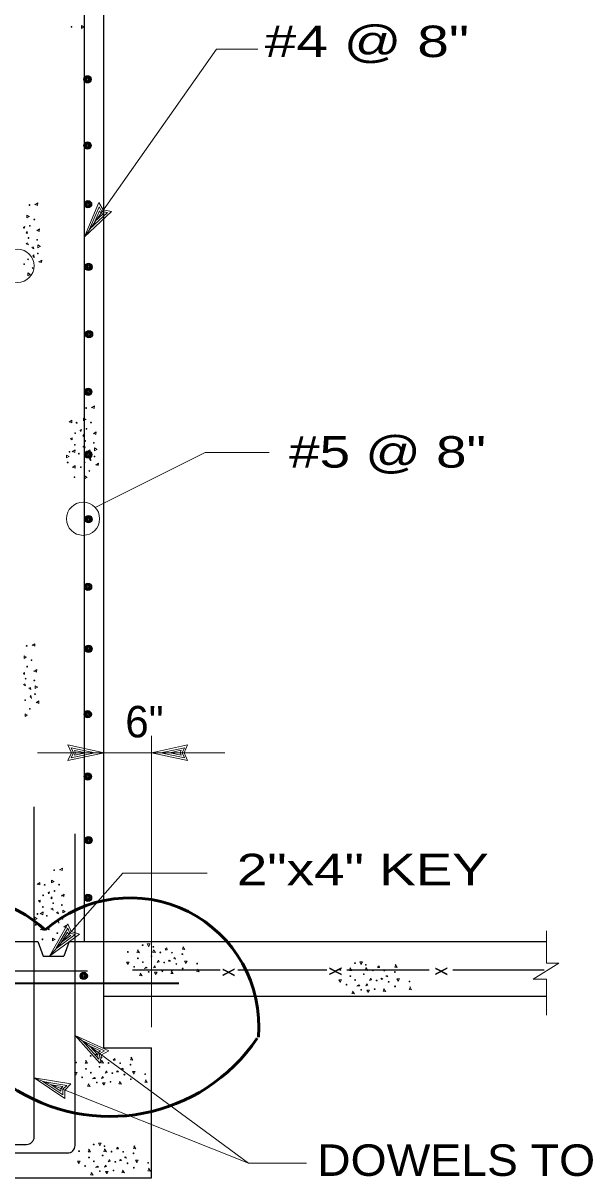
# Model space of a CAD drawing. Extents: x -28.1 to 13.9, y -16.1 to 13.9.
# Drawn here: x -8.685 to -6.424, y 2.995 to 7.58 of the extents above; entities that cross this region are included whole.
import ezdxf
from ezdxf.enums import TextEntityAlignment as Align

# ---------------------------------------------------------------- set-up
doc = ezdxf.new("R2010")
doc.units = 0
doc.header["$LTSCALE"] = 0.05
doc.layers.add('1', color=7, linetype='Continuous', lineweight=13)
doc.layers.add('2', color=7, linetype='Continuous', lineweight=13)

msp = doc.modelspace()

# ---------------------------------------------------------------- linework, layer by layer
at = {"layer": '1', "lineweight": 25}
for p, q in [((-8.36404, 3.51169), (-8.36404, 10.50069)), ((-8.44204, 3.93369), (-8.44204, 8.14169)), ((-8.64104, 3.15769), (-8.64104, 4.46769)), ((-8.47904, 3.12369), (-8.47904, 4.36069)), ((-8.62604, 3.93369), (-8.60504, 3.87569)), ((-8.50204, 3.93369), (-8.52304, 3.87569)), ((-8.50204, 3.93369), (-6.60804, 3.93369)), ((-8.60504, 3.87569), (-8.52304, 3.87569)), ((-9.59204, 3.81669), (-8.42904, 3.81669)), ((-8.25104, 3.82069), (-7.90304, 3.82069)), ((-7.83304, 3.82069), (-7.47904, 3.82069)), ((-7.40004, 3.82069), (-7.07404, 3.82069)), ((-6.98004, 3.82069), (-6.61704, 3.82069)), ((-8.36304, 3.71569), (-6.60804, 3.71569)), ((-8.36404, 3.51169), (-8.17604, 3.51169)), ((-8.17604, 2.99469), (-8.17604, 3.51169)), ((-9.57604, 3.12769), (-8.67104, 3.12769)), ((-8.81704, 3.09369), (-8.50904, 3.09369)), ((-9.67004, 2.99469), (-8.17604, 2.99469))]:
    msp.add_line(p, q, dxfattribs=at)
at = {"layer": '1'}
for p, q in [((-8.44204, 6.73169), (-8.38404, 6.86769)), ((-8.44204, 6.73169), (-8.33404, 6.83169)), ((-8.42104, 6.76169), (-8.38304, 6.85069)), ((-8.40004, 6.79169), (-8.38204, 6.83369)), ((-8.38304, 6.85069), (-8.37204, 6.83169)), ((-8.38204, 6.83369), (-8.37604, 6.82469)), ((-8.37204, 6.83169), (-8.35004, 6.82769)), ((-8.42104, 6.76169), (-8.35004, 6.82769)), ((-8.40004, 6.79169), (-8.36704, 6.82269)), ((-8.37604, 6.82469), (-8.36704, 6.82269)), ((-8.17604, 3.59369), (-8.17604, 4.74969)), ((-8.36304, 4.68269), (-8.50704, 4.71369)), ((-8.36304, 4.68269), (-8.50704, 4.65169)), ((-8.40004, 4.68269), (-8.49404, 4.70269)), ((-8.48504, 4.68269), (-8.49404, 4.70269)), ((-8.40004, 4.68269), (-8.49404, 4.66269)), ((-8.49404, 4.66269), (-8.48504, 4.68269)), ((-8.43604, 4.68269), (-8.48104, 4.69169)), ((-8.47704, 4.68269), (-8.48104, 4.69169)), ((-8.43604, 4.68269), (-8.48104, 4.67269)), ((-8.48104, 4.67269), (-8.47704, 4.68269)), ((-8.17604, 4.68269), (-8.03204, 4.71369)), ((-8.17604, 4.68269), (-8.03204, 4.65169)), ((-8.13904, 4.68269), (-8.04504, 4.70269)), ((-8.13904, 4.68269), (-8.04504, 4.66269)), ((-8.10304, 4.68269), (-8.05804, 4.69269)), ((-8.10304, 4.68269), (-8.05804, 4.67369)), ((-8.05804, 4.69269), (-8.06204, 4.68269)), ((-8.06204, 4.68269), (-8.05804, 4.67369)), ((-8.04504, 4.70269), (-8.05404, 4.68269)), ((-8.05404, 4.68269), (-8.04504, 4.66269)), ((-8.58004, 3.87569), (-8.50804, 4.00369)), ((-8.58004, 3.87569), (-8.46104, 3.96269)), ((-8.55504, 3.90369), (-8.50804, 3.98669)), ((-8.55504, 3.90369), (-8.47804, 3.96069)), ((-8.53204, 3.93069), (-8.50904, 3.97069)), ((-8.53204, 3.93069), (-8.49504, 3.95769)), ((-8.50904, 3.97069), (-8.50404, 3.96069)), ((-8.50804, 3.98669), (-8.49904, 3.96669)), ((-8.50404, 3.96069), (-8.49504, 3.95769)), ((-8.49904, 3.96669), (-8.47804, 3.96069)), ((-6.60804, 3.84769), (-6.60804, 3.97569)), ((-6.66004, 3.78369), (-6.55904, 3.84769)), ((-6.60804, 3.84769), (-6.55904, 3.84769)), ((-6.66004, 3.78369), (-6.60804, 3.78369)), ((-6.60804, 3.64069), (-6.60804, 3.78369)), ((-8.47904, 3.56069), (-7.79004, 3.05269)), ((-8.47904, 3.56069), (-8.34504, 3.49969)), ((-8.47904, 3.56069), (-8.38104, 3.45069)), ((-8.44904, 3.53869), (-8.36204, 3.49869)), ((-8.44904, 3.53869), (-8.38504, 3.46669)), ((-8.42004, 3.51769), (-8.38904, 3.48369)), ((-8.42004, 3.51769), (-8.37804, 3.49869)), ((-8.38704, 3.49269), (-8.38904, 3.48369)), ((-8.37804, 3.49869), (-8.38704, 3.49269)), ((-8.38104, 3.48869), (-8.38504, 3.46669)), ((-8.36204, 3.49869), (-8.38104, 3.48869)), ((-8.64104, 3.39169), (-7.79004, 3.05269)), ((-8.64104, 3.39169), (-8.49604, 3.36769)), ((-8.64104, 3.39169), (-8.51904, 3.30969)), ((-8.60704, 3.37769), (-8.51204, 3.36169)), ((-8.60704, 3.37769), (-8.52704, 3.32469)), ((-8.57304, 3.36469), (-8.53504, 3.33969)), ((-8.57304, 3.36469), (-8.52804, 3.35769)), ((-8.52804, 3.35769), (-8.53504, 3.34969)), ((-8.53504, 3.34969), (-8.53504, 3.33969)), ((-8.51204, 3.36169), (-8.52804, 3.34669)), ((-8.52804, 3.34669), (-8.52704, 3.32469)), ((-7.79004, 3.05269), (-7.56004, 3.05269))]:
    msp.add_line(p, q, dxfattribs=at)
at = {"layer": '1', "lineweight": 35}
msp.add_line((-9.24232, 3.76845), (-8.0669, 3.76845), dxfattribs=at)
at = {"layer": '1'}
for points in [[(-8.44204, 6.73169), (-7.91704, 7.47569), (-7.75404, 7.47569)], [(-8.38404, 6.86769), (-8.36704, 6.83769), (-8.33404, 6.83169)], [(-8.39904, 5.65669), (-7.96204, 5.87469), (-7.70804, 5.87469)], [(-8.62804, 4.68269), (-8.36304, 4.68269), (-8.17604, 4.68269), (-7.88404, 4.68269)], [(-8.50704, 4.65169), (-8.49304, 4.68269), (-8.50704, 4.71369)], [(-8.03204, 4.71369), (-8.04604, 4.68269), (-8.03204, 4.65169)], [(-8.58004, 3.87569), (-8.28904, 4.20469), (-7.95504, 4.20469)], [(-8.50804, 4.00369), (-8.49404, 3.97269), (-8.46104, 3.96269)], [(-8.34504, 3.49969), (-8.37404, 3.48369), (-8.38104, 3.45069)], [(-8.49604, 3.36769), (-8.52004, 3.34369), (-8.51904, 3.30969)]]:
    msp.add_lwpolyline(points, dxfattribs=at)
at = {"layer": '1', "lineweight": 25}
msp.add_lwpolyline([(-9.67004, 3.91269), (-8.75304, 3.93369), (-8.62604, 3.93369)], dxfattribs=at)
for centre, radius in [((-8.42957, 7.35641), 0.01445), ((-8.42957, 7.35641), 0.01121), ((-8.42957, 7.35641), 0.00822), ((-8.42957, 7.35641), 0.00415), ((-8.42957, 7.09341), 0.01445), ((-8.42957, 7.09341), 0.01121), ((-8.42957, 7.09341), 0.00822), ((-8.42957, 7.09341), 0.00415), ((-8.42757, 6.86041), 0.01445), ((-8.42757, 6.86041), 0.01121), ((-8.42757, 6.86041), 0.00822), ((-8.42757, 6.86041), 0.00415), ((-8.42557, 6.61141), 0.01445), ((-8.42557, 6.61141), 0.01121), ((-8.42557, 6.61141), 0.00822), ((-8.42557, 6.61141), 0.00415), ((-8.42357, 6.34441), 0.01445), ((-8.42357, 6.34441), 0.01121), ((-8.42357, 6.34441), 0.00822), ((-8.42357, 6.34441), 0.00415), ((-8.42657, 6.11541), 0.01445), ((-8.42657, 6.11541), 0.01121), ((-8.42657, 6.11541), 0.00822), ((-8.42657, 6.11541), 0.00415), ((-8.42657, 5.86641), 0.01445), ((-8.42657, 5.86641), 0.01121), ((-8.42657, 5.86641), 0.00822), ((-8.42657, 5.86641), 0.00415), ((-8.42557, 5.61041), 0.01445), ((-8.42557, 5.61041), 0.01121), ((-8.42557, 5.61041), 0.00822), ((-8.42557, 5.61041), 0.00415), ((-8.42757, 5.34141), 0.01445), ((-8.42757, 5.34141), 0.01121), ((-8.42757, 5.34141), 0.00822), ((-8.42757, 5.34141), 0.00415), ((-8.42557, 5.09541), 0.01445), ((-8.42557, 5.09541), 0.01121), ((-8.42557, 5.09541), 0.00822), ((-8.42557, 5.09541), 0.00415), ((-8.42857, 4.83541), 0.01445), ((-8.42857, 4.83541), 0.01121), ((-8.42857, 4.83541), 0.00822), ((-8.42857, 4.83541), 0.00415), ((-8.42857, 4.58841), 0.01445), ((-8.42857, 4.58841), 0.01121), ((-8.42857, 4.58841), 0.00822), ((-8.42857, 4.58841), 0.00415), ((-8.42557, 4.33541), 0.01445), ((-8.42557, 4.33541), 0.01121), ((-8.42557, 4.33541), 0.00822), ((-8.42557, 4.33541), 0.00415), ((-8.42757, 4.10641), 0.01445), ((-8.42757, 4.10641), 0.01121), ((-8.42757, 4.10641), 0.00822), ((-8.42757, 4.10641), 0.00415), ((-8.44457, 3.79641), 0.01445), ((-8.44457, 3.79641), 0.01121), ((-8.44457, 3.79641), 0.00822), ((-8.44457, 3.79641), 0.00415)]:
    msp.add_circle(centre, radius, dxfattribs=at)
at = {"layer": '1'}
for centre in [(-8.70704, 6.61569), (-8.44704, 5.61169)]:
    msp.add_circle(centre, 0.0658, dxfattribs=at)
at = {"layer": '1', "lineweight": 53}
for centre, radius, start, end in [((-8.94381, 3.60375), 0.5106, 47.30804, 164.27765), ((-8.25982, 3.59625), 0.51052, 355.19084, 131.42382), ((-8.34111, 3.94628), 0.70763, 235.88932, 325.85163)]:
    msp.add_arc(centre, radius, start, end, dxfattribs=at)
at = {"layer": '1', "lineweight": 25}
for centre in [(-8.67104, 3.15769), (-8.50904, 3.12369)]:
    msp.add_arc(centre, 0.03, 270, 0, dxfattribs=at)
at = {"layer": '2'}
for p, q in [((-8.49204, 5.92469), (-8.49704, 5.93069)), ((-8.61904, 4.08969), (-8.62404, 4.09569)), ((-8.12104, 3.90269), (-8.11504, 3.90769)), ((-7.27804, 3.83169), (-7.27204, 3.83669)), ((-8.32704, 3.46369), (-8.32104, 3.46869)), ((-8.31504, 3.11169), (-8.30904, 3.11669))]:
    msp.add_line(p, q, dxfattribs=at)
for points in [[(-8.44504, 7.56369), (-8.45304, 7.55869), (-8.45304, 7.56969), (-8.44304, 7.56369)], [(-8.63804, 6.86069), (-8.62804, 6.85569), (-8.62704, 6.86569), (-8.63804, 6.85869)], [(-8.66204, 6.81169), (-8.67004, 6.80669), (-8.67004, 6.81769), (-8.66004, 6.81169)], [(-8.68204, 6.76369), (-8.68404, 6.76869), (-8.67804, 6.77169), (-8.68104, 6.76369)], [(-8.66904, 6.74369), (-8.67304, 6.74669), (-8.66904, 6.75169), (-8.66804, 6.74469)], [(-8.63104, 6.75769), (-8.62104, 6.75269), (-8.62004, 6.76269), (-8.63104, 6.75469)], [(-8.61704, 6.69269), (-8.62604, 6.68769), (-8.62604, 6.69869), (-8.61604, 6.69269)], [(-8.64304, 6.65069), (-8.64604, 6.65569), (-8.64304, 6.65969), (-8.64104, 6.64769)], [(-8.62204, 6.63369), (-8.61204, 6.62869), (-8.61104, 6.63869), (-8.62204, 6.63069)], [(-8.65804, 6.58169), (-8.66604, 6.57669), (-8.66604, 6.58769), (-8.65604, 6.58169)], [(-8.41304, 6.05469), (-8.40304, 6.04969), (-8.40204, 6.05969), (-8.41304, 6.05269)], [(-8.43704, 6.00569), (-8.44504, 6.00069), (-8.44504, 6.01169), (-8.43504, 6.00569)], [(-8.50204, 5.99769), (-8.49204, 5.99269), (-8.49104, 6.00269), (-8.50204, 5.99469)], [(-8.45704, 5.95769), (-8.45904, 5.96269), (-8.45304, 5.96569), (-8.45604, 5.95769)], [(-8.49704, 5.93069), (-8.49004, 5.93269), (-8.49004, 5.92469)], [(-8.44404, 5.93769), (-8.44804, 5.94069), (-8.44404, 5.94569), (-8.44304, 5.93869)], [(-8.40604, 5.95169), (-8.39604, 5.94669), (-8.39504, 5.95669), (-8.40604, 5.94869)], [(-8.49004, 5.87969), (-8.48004, 5.87469), (-8.47904, 5.88569), (-8.49004, 5.87769)], [(-8.39204, 5.88669), (-8.40104, 5.88169), (-8.40104, 5.89269), (-8.39104, 5.88669)], [(-8.50404, 5.85869), (-8.51304, 5.85369), (-8.51304, 5.86469), (-8.50204, 5.85869)], [(-8.41804, 5.84469), (-8.42104, 5.84969), (-8.41804, 5.85369), (-8.41604, 5.84169)], [(-8.39704, 5.82769), (-8.38704, 5.82269), (-8.38604, 5.83269), (-8.39704, 5.82469)], [(-8.48904, 5.81769), (-8.47904, 5.81269), (-8.47804, 5.82269), (-8.48904, 5.81469)], [(-8.43304, 5.77569), (-8.44104, 5.77069), (-8.44104, 5.78169), (-8.43104, 5.77569)], [(-8.64904, 5.11069), (-8.63904, 5.10569), (-8.63804, 5.11569), (-8.64904, 5.10869)], [(-8.67304, 5.06169), (-8.68104, 5.05669), (-8.68104, 5.06769), (-8.67104, 5.06169)], [(-8.68004, 4.99369), (-8.68404, 4.99669), (-8.68004, 5.00169), (-8.67904, 4.99469)], [(-8.64204, 5.00769), (-8.63204, 5.00269), (-8.63104, 5.01269), (-8.64204, 5.00469)], [(-8.65404, 4.90069), (-8.65704, 4.90569), (-8.65404, 4.90969), (-8.65204, 4.89769)], [(-8.62804, 4.94269), (-8.63704, 4.93769), (-8.63704, 4.94869), (-8.62704, 4.94269)], [(-8.63304, 4.88369), (-8.62304, 4.87869), (-8.62204, 4.88869), (-8.63304, 4.88069)], [(-8.66904, 4.83169), (-8.67704, 4.82669), (-8.67704, 4.83769), (-8.66704, 4.83169)], [(-8.54004, 4.21969), (-8.53004, 4.21469), (-8.52904, 4.22469), (-8.54004, 4.21769)], [(-8.56404, 4.17069), (-8.57204, 4.16569), (-8.57204, 4.17669), (-8.56204, 4.17069)], [(-8.62904, 4.16269), (-8.61904, 4.15769), (-8.61804, 4.16769), (-8.62904, 4.15969)], [(-8.58404, 4.12269), (-8.58604, 4.12769), (-8.58004, 4.13069), (-8.58304, 4.12269)], [(-8.62404, 4.09569), (-8.61704, 4.09769), (-8.61704, 4.08969)], [(-8.57104, 4.10269), (-8.57504, 4.10569), (-8.57104, 4.11069), (-8.57004, 4.10369)], [(-8.53304, 4.11669), (-8.52304, 4.11169), (-8.52204, 4.12169), (-8.53304, 4.11369)], [(-8.61704, 4.04469), (-8.60704, 4.03969), (-8.60604, 4.05069), (-8.61704, 4.04269)], [(-8.51904, 4.05169), (-8.52804, 4.04669), (-8.52804, 4.05769), (-8.51804, 4.05169)], [(-8.63104, 4.02369), (-8.64004, 4.01869), (-8.64004, 4.02969), (-8.62904, 4.02369)], [(-8.54504, 4.00969), (-8.54804, 4.01469), (-8.54504, 4.01869), (-8.54304, 4.00669)], [(-8.52404, 3.99269), (-8.51404, 3.98769), (-8.51304, 3.99769), (-8.52404, 3.98969)], [(-8.61604, 3.98269), (-8.60604, 3.97769), (-8.60504, 3.98769), (-8.61604, 3.97969)], [(-8.56004, 3.94069), (-8.56804, 3.93569), (-8.56804, 3.94669), (-8.55804, 3.94069)], [(-8.22804, 3.89969), (-8.23304, 3.88969), (-8.22304, 3.88869), (-8.23104, 3.89969)], [(-8.18704, 3.91469), (-8.19204, 3.92369), (-8.18104, 3.92369), (-8.18704, 3.91269)], [(-8.16604, 3.90069), (-8.17104, 3.89069), (-8.16004, 3.88969), (-8.16804, 3.90069)], [(-8.11504, 3.90769), (-8.11304, 3.90069), (-8.12104, 3.90069)], [(-8.04804, 3.91269), (-8.05304, 3.90269), (-8.04304, 3.90169), (-8.05104, 3.91269)], [(-8.27004, 3.84369), (-8.27504, 3.85169), (-8.26404, 3.85169), (-8.27004, 3.84169)], [(-8.10804, 3.85469), (-8.10504, 3.85869), (-8.10004, 3.85469), (-8.10704, 3.85369)], [(-8.08804, 3.86769), (-8.08304, 3.86969), (-8.08004, 3.86369), (-8.08804, 3.86669)], [(-8.04004, 3.84769), (-8.04504, 3.85569), (-8.03404, 3.85569), (-8.04004, 3.84569)], [(-7.34404, 3.84369), (-7.34904, 3.85269), (-7.33804, 3.85269), (-7.34404, 3.84169)], [(-8.21804, 3.80769), (-8.22304, 3.79769), (-8.21304, 3.79669), (-8.22104, 3.80769)], [(-8.20104, 3.82869), (-8.19604, 3.83169), (-8.19204, 3.82869), (-8.20404, 3.82669)], [(-8.15904, 3.80269), (-8.16404, 3.81169), (-8.15304, 3.81169), (-8.15904, 3.80169)], [(-8.09404, 3.81669), (-8.09904, 3.80669), (-8.08904, 3.80569), (-8.09704, 3.81669)], [(-7.99104, 3.82369), (-7.99604, 3.81369), (-7.98604, 3.81269), (-7.99304, 3.82369)], [(-7.38504, 3.82869), (-7.39004, 3.81869), (-7.38004, 3.81769), (-7.38804, 3.82869)], [(-7.32304, 3.82969), (-7.32804, 3.81969), (-7.31704, 3.81869), (-7.32504, 3.82969)], [(-7.27204, 3.83669), (-7.27004, 3.82969), (-7.27804, 3.82969)], [(-7.20504, 3.84169), (-7.21004, 3.83169), (-7.20004, 3.83069), (-7.20804, 3.84169)], [(-7.42704, 3.77269), (-7.43204, 3.78069), (-7.42104, 3.78069), (-7.42704, 3.77069)], [(-7.35804, 3.75769), (-7.35304, 3.76069), (-7.34904, 3.75769), (-7.36104, 3.75569)], [(-7.26504, 3.78369), (-7.26204, 3.78769), (-7.25704, 3.78369), (-7.26404, 3.78269)], [(-7.24504, 3.79669), (-7.24004, 3.79869), (-7.23704, 3.79269), (-7.24504, 3.79569)], [(-7.19704, 3.77669), (-7.20204, 3.78469), (-7.19104, 3.78469), (-7.19704, 3.77469)], [(-7.37504, 3.73669), (-7.38004, 3.72669), (-7.37004, 3.72569), (-7.37804, 3.73669)], [(-7.31604, 3.73169), (-7.32104, 3.74069), (-7.31004, 3.74069), (-7.31604, 3.73069)], [(-7.25104, 3.74569), (-7.25604, 3.73569), (-7.24604, 3.73469), (-7.25404, 3.74569)], [(-7.14804, 3.75269), (-7.15304, 3.74269), (-7.14304, 3.74169), (-7.15004, 3.75269)], [(-8.39304, 3.47569), (-8.39804, 3.48469), (-8.38704, 3.48469), (-8.39304, 3.47369)], [(-8.43404, 3.46069), (-8.43904, 3.45069), (-8.42904, 3.44969), (-8.43704, 3.46069)], [(-8.37204, 3.46169), (-8.37704, 3.45169), (-8.36604, 3.45069), (-8.37404, 3.46169)], [(-8.32104, 3.46869), (-8.31904, 3.46169), (-8.32704, 3.46169)], [(-8.25404, 3.47369), (-8.25904, 3.46369), (-8.24904, 3.46269), (-8.25704, 3.47369)], [(-8.47604, 3.40469), (-8.48104, 3.41269), (-8.47004, 3.41269), (-8.47604, 3.40269)], [(-8.31404, 3.41569), (-8.31104, 3.41969), (-8.30604, 3.41569), (-8.31304, 3.41469)], [(-8.29404, 3.42869), (-8.28904, 3.43069), (-8.28604, 3.42469), (-8.29404, 3.42769)], [(-8.24604, 3.40869), (-8.25104, 3.41669), (-8.24004, 3.41669), (-8.24604, 3.40669)], [(-8.42404, 3.36869), (-8.42904, 3.35869), (-8.41904, 3.35769), (-8.42704, 3.36869)], [(-8.40704, 3.38969), (-8.40204, 3.39269), (-8.39804, 3.38969), (-8.41004, 3.38769)], [(-8.36504, 3.36369), (-8.37004, 3.37269), (-8.35904, 3.37269), (-8.36504, 3.36269)], [(-8.30004, 3.37769), (-8.30504, 3.36769), (-8.29504, 3.36669), (-8.30304, 3.37769)], [(-8.19704, 3.38469), (-8.20204, 3.37469), (-8.19204, 3.37369), (-8.19904, 3.38469)], [(-8.38104, 3.12369), (-8.38604, 3.13269), (-8.37504, 3.13269), (-8.38104, 3.12169)], [(-8.24204, 3.12169), (-8.24704, 3.11169), (-8.23704, 3.11069), (-8.24504, 3.12169)], [(-8.42204, 3.10869), (-8.42704, 3.09869), (-8.41704, 3.09769), (-8.42504, 3.10869)], [(-8.36004, 3.10969), (-8.36504, 3.09969), (-8.35404, 3.09869), (-8.36204, 3.10969)], [(-8.30904, 3.11669), (-8.30704, 3.10969), (-8.31504, 3.10969)], [(-8.28204, 3.07669), (-8.27704, 3.07869), (-8.27404, 3.07269), (-8.28204, 3.07569)], [(-8.46404, 3.05269), (-8.46904, 3.06069), (-8.45804, 3.06069), (-8.46404, 3.05069)], [(-8.39504, 3.03769), (-8.39004, 3.04069), (-8.38604, 3.03769), (-8.39804, 3.03569)], [(-8.30204, 3.06369), (-8.29904, 3.06769), (-8.29404, 3.06369), (-8.30104, 3.06269)], [(-8.23404, 3.05669), (-8.23904, 3.06469), (-8.22804, 3.06469), (-8.23404, 3.05469)], [(-8.18504, 3.03269), (-8.19004, 3.02269), (-8.18004, 3.02169), (-8.18704, 3.03269)], [(-8.41204, 3.01669), (-8.41704, 3.00669), (-8.40704, 3.00569), (-8.41504, 3.01669)], [(-8.35304, 3.01169), (-8.35804, 3.02069), (-8.34704, 3.02069), (-8.35304, 3.01069)], [(-8.28804, 3.02569), (-8.29304, 3.01569), (-8.28304, 3.01469), (-8.29104, 3.02569)]]:
    msp.add_lwpolyline(points, dxfattribs=at)
for points in [[(-8.66404, 6.69869), (-8.67304, 6.70369), (-8.66704, 6.70669)], [(-8.64304, 6.68369), (-8.65104, 6.68869), (-8.64504, 6.69169)], [(-8.43904, 5.89269), (-8.44804, 5.89769), (-8.44204, 5.90069)], [(-8.41804, 5.87769), (-8.42604, 5.88269), (-8.42004, 5.88569)], [(-8.67504, 4.94869), (-8.68404, 4.95369), (-8.67804, 4.95669)], [(-8.65404, 4.93369), (-8.66204, 4.93869), (-8.65604, 4.94169)], [(-8.56604, 4.05769), (-8.57504, 4.06269), (-8.56904, 4.06569)], [(-8.54504, 4.04269), (-8.55304, 4.04769), (-8.54704, 4.05069)], [(-8.15304, 3.84969), (-8.14804, 3.85869), (-8.14504, 3.85269)], [(-8.16804, 3.82869), (-8.16304, 3.83669), (-8.16004, 3.83069)], [(-7.32504, 3.75769), (-7.32004, 3.76569), (-7.31704, 3.75969)], [(-7.31004, 3.77869), (-7.30504, 3.78769), (-7.30204, 3.78169)], [(-8.37404, 3.38969), (-8.36904, 3.39769), (-8.36604, 3.39169)], [(-8.35904, 3.41069), (-8.35404, 3.41969), (-8.35104, 3.41369)], [(-8.36204, 3.03769), (-8.35704, 3.04569), (-8.35404, 3.03969)], [(-8.34704, 3.05869), (-8.34204, 3.06769), (-8.33904, 3.06169)]]:
    msp.add_lwpolyline(points, close=True, dxfattribs=at)
for centre in [(-8.49317, 7.56469), (-8.65992, 6.85719), (-8.64042, 6.79994), (-8.65817, 6.77469), (-8.66392, 6.72669), (-8.62942, 6.71919), (-8.62692, 6.66519), (-8.68092, 6.62244), (-8.66567, 6.64169), (-8.64717, 6.60719), (-8.43492, 6.05119), (-8.47267, 5.99294), (-8.43317, 5.96869), (-8.41542, 5.99394), (-8.47842, 5.95169), (-8.43892, 5.92069), (-8.40442, 5.91319), (-8.50117, 5.87769), (-8.47942, 5.90544), (-8.46417, 5.87019), (-8.50792, 5.83494), (-8.44067, 5.83569), (-8.40192, 5.85919), (-8.48117, 5.77669), (-8.45592, 5.81644), (-8.42217, 5.80119), (-8.67092, 5.10719), (-8.65142, 5.04994), (-8.66917, 5.02469), (-8.67492, 4.97669), (-8.64042, 4.96919), (-8.63792, 4.91519), (-8.67667, 4.89169), (-8.65817, 4.85719), (-8.56192, 4.21619), (-8.59967, 4.15794), (-8.56017, 4.13369), (-8.54242, 4.15894), (-8.60542, 4.11669), (-8.56592, 4.08569), (-8.62817, 4.04269), (-8.60642, 4.07044), (-8.59117, 4.03519), (-8.53142, 4.07819), (-8.63492, 3.99994), (-8.56767, 4.00069), (-8.52892, 4.02419), (-8.60817, 3.94169), (-8.58292, 3.98144), (-8.54917, 3.96619), (-8.21079, 3.91856), (-8.16804, 3.91181), (-8.26904, 3.89181), (-8.22929, 3.86656), (-8.21004, 3.85131), (-8.17554, 3.87481), (-8.14029, 3.89006), (-8.09404, 3.88906), (-8.05279, 3.88331), (-8.24454, 3.83281), (-8.18654, 3.81256), (-8.13254, 3.81506), (-8.12504, 3.84956), (-8.07704, 3.84381), (-8.05179, 3.82606), (-7.99454, 3.84556), (-7.42604, 3.82081), (-7.36779, 3.84756), (-7.32504, 3.84081), (-7.29729, 3.81906), (-7.25104, 3.81806), (-7.20979, 3.81231), (-7.40154, 3.76181), (-7.38629, 3.79556), (-7.36704, 3.78031), (-7.33254, 3.80381), (-7.28204, 3.77856), (-7.23404, 3.77281), (-7.15154, 3.77456), (-7.34354, 3.74156), (-7.28954, 3.74406), (-7.20879, 3.75506), (-8.47504, 3.45281), (-8.41679, 3.47956), (-8.37404, 3.47281), (-8.34629, 3.45106), (-8.30004, 3.45006), (-8.25879, 3.44431), (-8.45054, 3.39381), (-8.43529, 3.42756), (-8.41604, 3.41231), (-8.38154, 3.43581), (-8.33104, 3.41056), (-8.28304, 3.40481), (-8.20054, 3.40656), (-8.39254, 3.37356), (-8.33854, 3.37606), (-8.25779, 3.38706), (-8.40479, 3.12756), (-8.36204, 3.12081), (-8.46304, 3.10081), (-8.42329, 3.07556), (-8.36954, 3.08381), (-8.33429, 3.09906), (-8.28804, 3.09806), (-8.24679, 3.09231), (-8.43854, 3.04181), (-8.40404, 3.06031), (-8.31904, 3.05856), (-8.27104, 3.05281), (-8.24579, 3.03506), (-8.18854, 3.05456), (-8.38054, 3.02156), (-8.32654, 3.02406)]:
    msp.add_circle(centre, 0.00162, dxfattribs=at)

# ---------------------------------------------------------------- texts
at = {"layer": '1'}
for s, width, p in [('#4 @ 8"', 1.35, (-7.72604, 7.44469)), ('#5 @ 8"', 1.3, (-7.62904, 5.81469)), ('DOWELS TO', 1.1, (-7.51804, 3.00269))]:
    msp.add_text(s, height=0.125, dxfattribs=dict(at, width=width)).set_placement(p)
msp.add_text('6"', height=0.125, dxfattribs=at).set_placement((-8.20342, 4.74369), align=Align.CENTER)
at = {"layer": '1', "width": 1.3}
msp.add_text('2"x4" KEY', height=0.125, dxfattribs=at).set_placement((-6.83705, 4.15669), align=Align.RIGHT)
at = {"layer": '1', "width": 0.8}
for p in [(-7.84504, 3.81111), (-7.42104, 3.81511), (-7.00104, 3.81511)]:
    msp.add_text('x', height=0.063, rotation=90, dxfattribs=at).set_placement(p, align=Align.CENTER)

doc.saveas('drawing.dxf')
